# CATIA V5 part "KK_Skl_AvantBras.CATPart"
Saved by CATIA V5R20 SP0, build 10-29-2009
Part number: skl_av_bras
Bounding box of the stored display mesh (mm): x 0 to 500, y 0 to 0, z -80 to -40
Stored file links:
  G:\Khaled_CFAO_2011\ST2M\ST2M_GR2\tcorbin\Khaled\CAD_ThinkMOTION\KK_Skl_AvantBras.CATPart
  F:\Thinkmotionperso\assemblage robot\ass_skl_robot.CATProduct
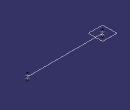
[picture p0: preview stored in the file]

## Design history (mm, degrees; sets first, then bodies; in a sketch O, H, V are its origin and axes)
External parameters (linked from other documents)
  `External.longueur avbras` = 500 mm
Set1
  Plane1 "plan_extr_av_bras": type Offset, RefPlane xy-plane, Offset -60
  Point1 "point_perçage_1": type OnPlane, Support Plane1, H 0, V 0, Direction (1, 0, 0)
  Point2 "point_perçage_2": type OnPlane, Support Plane1, H 500 {= `External.longueur avbras`}, V 0, Direction (1, 0, 0)
  Line1 "droite_long_av_bras": type PtPt, FirstPoint Point1, SecondPoint Point2
  Line2 "axe_perçage_1": type PtDir, RefPoint Point1, Direction xy-plane, Start -20, End 20
  Line3 "axe_perçage_2": type PtDir, RefPoint Point2, Direction xy-plane, Start -20, End 20
Body1 (main body)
